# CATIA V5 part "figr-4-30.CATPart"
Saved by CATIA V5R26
Part number: Part1
Bounding box of the stored display mesh (mm): x 0 to 40, y -49.816 to 150, z -49.907 to 49.907
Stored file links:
  D:\_Deepak\CATIA\CATIA V5-6R2016_Deepak\Resources\Part files\Partfiles\c04_catia_v5_6r2016_prt\figr-4-30.CATPart
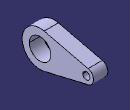
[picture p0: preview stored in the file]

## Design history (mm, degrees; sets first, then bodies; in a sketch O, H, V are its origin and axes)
Body1 (main body)
  Sketch1 on yz-plane, origin (0, 0, 0), H (0, 1, 0), V (0, 0, 1)
    arc A1 centre (0, 0) radius 50 from (11.5385, 48.6504) to (11.5385, -48.6504) ccw
    arc A2 centre (130, 0) radius 20 from (134.6154, -19.4602) to (134.6154, 19.4602) ccw
    point P1 (130, 0)
    line L1 (134.6154, 19.4602) -> (11.5385, 48.6504)
    line L2 (134.6154, -19.4602) -> (11.5385, -48.6504)
    circle A3 centre (0, 0) radius 30
    circle A4 centre (130, 0) radius 10
    point P6 (120, 0)
    coincidence: P1 H, A4 P6, P6 H
    tangency: L1 A2, L1 A1, L2 A2, L2 A1
  Pad1: profile Sketch1, direction (1, 0, 0), length 40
